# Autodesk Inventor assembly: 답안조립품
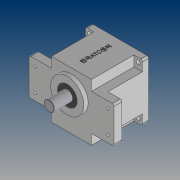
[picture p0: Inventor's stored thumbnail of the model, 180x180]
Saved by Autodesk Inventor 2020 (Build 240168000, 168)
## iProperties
Created: 2020-07
Part Number: 답안조립품
Document SubType Name: Assembly
Designer: PC312-
Author: PC312-
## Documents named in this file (10)
- C:\Users\PC312-\Desktop\700718V1005\답안조립품.iam
- C:\Users\PC312-\Desktop\700718V1005\본체.ipt
- C:\Users\PC312-\Desktop\700718V1005\커버.ipt
- C:\Users\PC312-\Desktop\700718V1005\오일 실 8 22 7.ipt
- C:\Users\PC312-\Desktop\700718V1005\베어링 608.ipt
- C:\Users\PC312-\Desktop\700718V1005\메인 축.ipt
- C:\Users\PC312-\Desktop\700718V1005\서브 축.ipt
- C:\Users\PC312-\Desktop\700718V1005\베어링 6003.ipt
- C:\Users\PC312-\Desktop\700718V1005\오일 실 17 32 8.ipt
- C:\Users\PC312-\Desktop\700718V1005\볼트 M4.ipt
